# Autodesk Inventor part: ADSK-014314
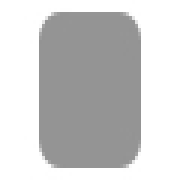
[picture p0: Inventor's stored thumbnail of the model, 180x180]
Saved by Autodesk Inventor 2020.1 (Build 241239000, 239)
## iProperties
Created: 2019-01
Part Number: ADSK-014314
Material: Stahl, weich
Document SubType Name: Modeling
Designer: lutzd
Language: de-DE
Size Designation: 5 x 39,384472 x 39,384472
Categories: <MemberInstance><Categories><Category DisplayName="Sonstige Bauteile" InternalName="5aa15e00-363f-49f2-933f-16f664388e3f" Mnemonic="OTHER"><Category DisplayName
Mass: 60.0398 g
Surface Area: 38.0412 cm^2
Volume: 7.64838 cm^3
Density: 7.85 g/cm^3
Appearance: Semi-Polished(8)
IsCustomPart: 1
DocNumber: ADSK-014314
Folder: 01 - Themengebiete\Simplification\01 - Packaging machine\
VDS_Category: 3D Komponenten
VDS_NumSchm: Autodesk
Dimensions: 39,4x39,4x5 mm
Mass: 0,06 kg
Title: end cap
Author: lutzd
Revision Number: -
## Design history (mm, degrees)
sketch "Sketch1"
  geometry: L1 (0, 20.175)-(0, -21.446); L2 (-20.203, 0)-(20.169, 0); L3 (-19.692, 19.692)-(19.692, 19.692); L4 (19.692, 19.692)-(19.692, -19.692); L5 (19.692, -19.692)-(-19.692, -19.692); L6 (-19.692, -19.692)-(-19.692, 19.692); 1 further point
  constraints: 12 end point, 2 horizontal, 2 parallel, 2 point on line, 1 perpendicular, 1 vertical
  dimensions: "d0" = 39.38447 distance between parallel lines of L5 L3 (= height); "d1" = 19.69224 distance between parallel lines of L2 L3 (= 0.5 x height); "d2" = 39.38447 distance between parallel lines of L6 L4 (= width); "d3" = 19.69224 distance between parallel lines of L6 L1 (= 0.5 x width)
extrude "Extrusion1" new body sketch "Sketch1" distance "d4" = 5 (= thickness); taper "d5" = 0 deg
fillet "Fillet1" dims "d6" = 5 (= fillet), "d7" = 0, "fillet" = 5 [user parameter; used in 1 equation term]
chamfer "Chamfer1" distance "d8" = 0 (computed from chamfer); stored, may be unused: second distance "d9" = 2, angle "d10" = 45 deg; dims "d11" = 0, "chamfer" = 0 [user parameter; used in 1 equation term]
body "Solid1"
other parameters: "thickness" = 5 [user parameter; used in 1 equation term], "width" = 39.38447 [user parameter; used in 2 equation terms], "height" = 39.38447 [user parameter; used in 2 equation terms]
